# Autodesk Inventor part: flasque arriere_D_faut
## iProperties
Created: 2011-10
Part Number: flasque arriere_D_faut
Document SubType Name: Modeling
Designer: Bruno
Author: Bruno
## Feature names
1. Base1
